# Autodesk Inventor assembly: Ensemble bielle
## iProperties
Shininess: 41.0
Length Units: 11269
Angle Units: 11279
Time Units: 11290
Mass Units: 11283
Length Display Precision: 3
Angle Display Precision: 2
Created: 2002-11
Part Number: Ensemble bielle
Document SubType Name: Assemblage
Designer: poste-2
Density: 0.0
Volumn: 0.0
Area: 0.0
PropertySet Name: Model Information
Control State: 0
Master: False
Checked Out: False
Author: poste-2
